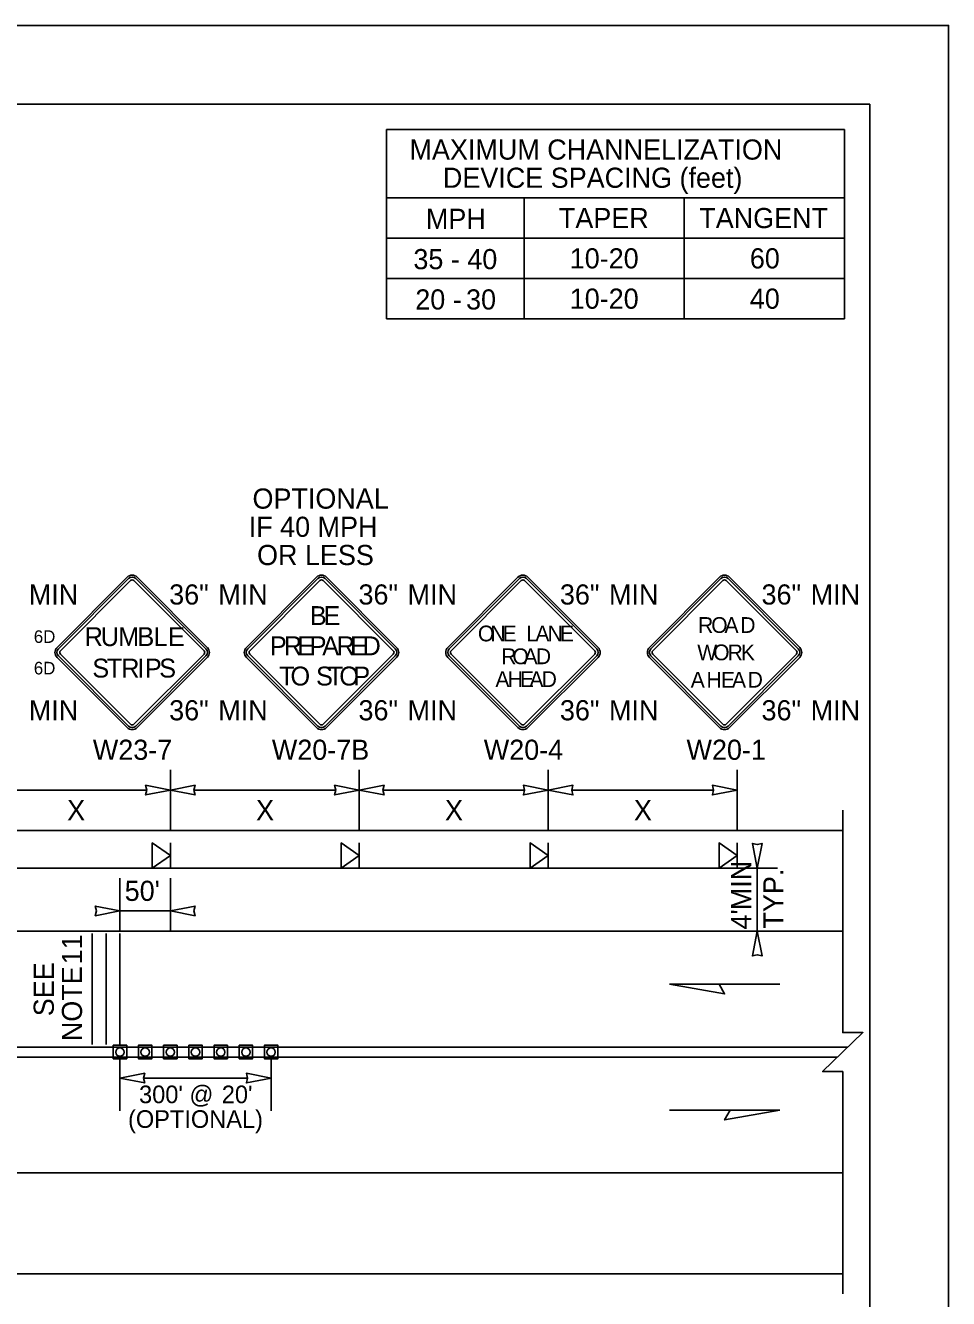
# Model space of a CAD drawing. Extents: x 99998.9 to 100095.7, y 99995 to 100010.7.
# Drawn here: x 100052.4 to 100056.06, y 100005.63 to 100010.69 of the extents above; entities that cross this region are included whole.
import ezdxf

# ---------------------------------------------------------------- set-up
doc = ezdxf.new("R2010")
doc.units = 0
for name, color, linetype in [('RD_ED_ShoulderPavedEdge', 7, 'Continuous'), ('RD_MK_LineDblYellowCenter', 7, 'Continuous'), ('RD_MK_LineEdgeWhite', 7, 'Continuous'), ('SH_GI_PlotLimits', 7, 'Continuous'), ('SH_GI_SheetBorder', 7, 'Continuous'), ('SH_TI_Tables', 7, 'Continuous'), ('TR_SN_ConstructionSigns', 7, 'Continuous'), ('TR_WZ_PortableSignMountBlk-Org', 7, 'Continuous'), ('TR_WZ_TrafficCone', 7, 'Continuous'), ('TR_WZ_WorkZoneDetails', 7, 'Continuous'), ('TR_WZ_WorkZoneTextCurrent', 7, 'Continuous')]:
    doc.layers.add(name, color=color, linetype=linetype)

msp = doc.modelspace()

# ---------------------------------------------------------------- linework, layer by layer
at = {"layer": 'RD_ED_ShoulderPavedEdge'}
for p, q in [((100040.1076, 100007.4923), (100055.6424, 100007.4923)), ((100040.1076, 100005.7323), (100055.6424, 100005.7323))]:
    msp.add_line(p, q, dxfattribs=at)
at = {"layer": 'RD_MK_LineDblYellowCenter'}
for p, q in [((100052.2733, 100006.6323), (100055.6631, 100006.6323)), ((100052.2733, 100006.5923), (100055.6218, 100006.5923))]:
    msp.add_line(p, q, dxfattribs=at)
at = {"layer": 'RD_MK_LineEdgeWhite'}
for p, q in [((100040.1076, 100007.0923), (100055.6424, 100007.0923)), ((100040.1076, 100006.1323), (100055.6424, 100006.1323))]:
    msp.add_line(p, q, dxfattribs=at)
at = {"layer": 'SH_GI_PlotLimits'}
msp.add_lwpolyline([(100039.0625, 99999.6875), (100056.0625, 99999.6875), (100056.0625, 100010.6875), (100039.0625, 100010.6875)], close=True, dxfattribs=at)
at = {"layer": 'SH_GI_SheetBorder'}
for p, q in [((100040, 100010.375), (100055.75, 100010.375)), ((100055.75, 100010.375), (100055.75, 100000))]:
    msp.add_line(p, q, dxfattribs=at)
at = {"layer": 'SH_TI_Tables'}
for p, q in [((100053.8318, 100010.275), (100055.65, 100010.275)), ((100053.8318, 100009.523), (100053.8318, 100010.275)), ((100055.65, 100009.523), (100055.65, 100010.275)), ((100053.8318, 100010.003), (100055.65, 100010.003)), ((100054.3773, 100009.523), (100054.3773, 100010.003)), ((100055.0136, 100009.523), (100055.0136, 100010.003)), ((100053.8318, 100009.843), (100054.3773, 100009.843)), ((100054.3773, 100009.843), (100055.0136, 100009.843)), ((100055.0136, 100009.843), (100055.65, 100009.843)), ((100053.8318, 100009.683), (100054.3773, 100009.683)), ((100054.3773, 100009.683), (100055.0136, 100009.683)), ((100055.0136, 100009.683), (100055.6472, 100009.683)), ((100053.8318, 100009.523), (100055.65, 100009.523))]:
    msp.add_line(p, q, dxfattribs=at)
at = {"layer": 'TR_SN_ConstructionSigns'}
for p, q in [((100052.8019, 100008.4972), (100052.5235, 100008.2188)), ((100052.8075, 100008.4917), (100052.529, 100008.2132)), ((100053.1146, 100008.2132), (100052.8362, 100008.4917)), ((100053.1201, 100008.2188), (100052.8417, 100008.4972)), ((100053.5535, 100008.4972), (100053.275, 100008.2188)), ((100053.559, 100008.4917), (100053.2806, 100008.2132)), ((100053.8661, 100008.2132), (100053.5877, 100008.4917)), ((100053.8717, 100008.2188), (100053.5932, 100008.4972)), ((100054.3532, 100008.4972), (100054.0747, 100008.2188)), ((100054.3587, 100008.4917), (100054.0803, 100008.2132)), ((100054.6658, 100008.2132), (100054.3874, 100008.4917)), ((100054.6714, 100008.2188), (100054.3929, 100008.4972)), ((100055.1535, 100008.4972), (100054.875, 100008.2188)), ((100055.159, 100008.4917), (100054.8806, 100008.2132)), ((100055.4661, 100008.2132), (100055.1877, 100008.4917)), ((100055.4717, 100008.2188), (100055.1932, 100008.4972)), ((100052.5368, 100008.2055), (100052.8152, 100008.4839)), ((100052.8285, 100008.4839), (100053.1069, 100008.2055)), ((100053.2883, 100008.2055), (100053.5667, 100008.4839)), ((100053.58, 100008.4839), (100053.8584, 100008.2055)), ((100054.088, 100008.2055), (100054.3664, 100008.4839)), ((100054.3797, 100008.4839), (100054.6581, 100008.2055)), ((100054.8883, 100008.2055), (100055.1667, 100008.4839)), ((100055.18, 100008.4839), (100055.4584, 100008.2055)), ((100052.529, 100008.1845), (100052.8075, 100007.9061)), ((100052.8152, 100007.9138), (100052.5368, 100008.1923)), ((100053.1069, 100008.1923), (100052.8285, 100007.9138)), ((100052.8362, 100007.9061), (100053.1146, 100008.1845)), ((100053.2806, 100008.1845), (100053.559, 100007.9061)), ((100053.5667, 100007.9138), (100053.2883, 100008.1923)), ((100053.8584, 100008.1923), (100053.58, 100007.9138)), ((100053.5877, 100007.9061), (100053.8661, 100008.1845)), ((100054.0803, 100008.1845), (100054.3587, 100007.9061)), ((100054.3664, 100007.9138), (100054.088, 100008.1923)), ((100054.6581, 100008.1923), (100054.3797, 100007.9138)), ((100054.3874, 100007.9061), (100054.6658, 100008.1845)), ((100054.8806, 100008.1845), (100055.159, 100007.9061)), ((100055.1667, 100007.9138), (100054.8883, 100008.1923)), ((100055.4584, 100008.1923), (100055.18, 100007.9138)), ((100055.1877, 100007.9061), (100055.4661, 100008.1845)), ((100052.5235, 100008.179), (100052.8019, 100007.9006)), ((100052.8417, 100007.9006), (100053.1201, 100008.179)), ((100053.275, 100008.179), (100053.5535, 100007.9006)), ((100053.5932, 100007.9006), (100053.8717, 100008.179)), ((100054.0747, 100008.179), (100054.3532, 100007.9006)), ((100054.3929, 100007.9006), (100054.6714, 100008.179)), ((100054.875, 100008.179), (100055.1535, 100007.9006)), ((100055.1932, 100007.9006), (100055.4717, 100008.179))]:
    msp.add_line(p, q, dxfattribs=at)
for centre, radius, start, end in [((100052.8218, 100008.4773), 0.0281, 45, 135), ((100052.8218, 100008.4773), 0.0203, 45, 135), ((100053.5733, 100008.4773), 0.0281, 45, 135), ((100053.5733, 100008.4773), 0.0203, 45, 135), ((100054.373, 100008.4773), 0.0281, 45, 135), ((100054.373, 100008.4773), 0.0203, 45, 135), ((100055.1733, 100008.4773), 0.0281, 45, 135), ((100055.1733, 100008.4773), 0.0203, 45, 135), ((100052.8218, 100008.4773), 0.00937, 45, 135), ((100053.5733, 100008.4773), 0.00937, 45, 135), ((100054.373, 100008.4773), 0.00937, 45, 135), ((100055.1733, 100008.4773), 0.00937, 45, 135), ((100052.5434, 100008.1989), 0.0281, 135, 225), ((100052.5434, 100008.1989), 0.0203, 135, 225), ((100052.5434, 100008.1989), 0.00937, 135, 225), ((100053.1003, 100008.1989), 0.00937, 315, 45), ((100053.1003, 100008.1989), 0.0203, 315, 45), ((100053.1003, 100008.1989), 0.0281, 315, 45), ((100053.2949, 100008.1989), 0.0281, 135, 225), ((100053.2949, 100008.1989), 0.0203, 135, 225), ((100053.2949, 100008.1989), 0.00937, 135, 225), ((100053.8518, 100008.1989), 0.00937, 315, 45), ((100053.8518, 100008.1989), 0.0203, 315, 45), ((100053.8518, 100008.1989), 0.0281, 315, 45), ((100054.0946, 100008.1989), 0.0281, 135, 225), ((100054.0946, 100008.1989), 0.0203, 135, 225), ((100054.0946, 100008.1989), 0.00937, 135, 225), ((100054.6515, 100008.1989), 0.00937, 315, 45), ((100054.6515, 100008.1989), 0.0203, 315, 45), ((100054.6515, 100008.1989), 0.0281, 315, 45), ((100054.8949, 100008.1989), 0.0281, 135, 225), ((100054.8949, 100008.1989), 0.0203, 135, 225), ((100054.8949, 100008.1989), 0.00937, 135, 225), ((100055.4518, 100008.1989), 0.00937, 315, 45), ((100055.4518, 100008.1989), 0.0203, 315, 45), ((100055.4518, 100008.1989), 0.0281, 315, 45), ((100052.8218, 100007.9205), 0.0281, 225, 315), ((100052.8218, 100007.9205), 0.0203, 225, 315), ((100052.8218, 100007.9205), 0.00937, 225, 315), ((100053.5733, 100007.9205), 0.0281, 225, 315), ((100053.5733, 100007.9205), 0.0203, 225, 315), ((100053.5733, 100007.9205), 0.00937, 225, 315), ((100054.373, 100007.9205), 0.0281, 225, 315), ((100054.373, 100007.9205), 0.0203, 225, 315), ((100054.373, 100007.9205), 0.00937, 225, 315), ((100055.1733, 100007.9205), 0.0281, 225, 315), ((100055.1733, 100007.9205), 0.0203, 225, 315), ((100055.1733, 100007.9205), 0.00937, 225, 315)]:
    msp.add_arc(centre, radius, start, end, dxfattribs=at)
at = {"layer": 'TR_WZ_PortableSignMountBlk-Org'}
for p, q in [((100052.9733, 100007.4422), (100052.9733, 100007.3422)), ((100053.7233, 100007.4422), (100053.7233, 100007.3422)), ((100054.4733, 100007.4422), (100054.4733, 100007.3422)), ((100055.2233, 100007.4422), (100055.2233, 100007.3422))]:
    msp.add_line(p, q, dxfattribs=at)
for points in [[(100052.9733, 100007.3923), (100052.9015, 100007.3422), (100052.9015, 100007.4422)], [(100053.7233, 100007.3923), (100053.6515, 100007.3422), (100053.6515, 100007.4422)], [(100054.4733, 100007.3923), (100054.4015, 100007.3422), (100054.4015, 100007.4422)], [(100055.2233, 100007.3923), (100055.1515, 100007.3422), (100055.1515, 100007.4422)]]:
    msp.add_lwpolyline(points, close=True, dxfattribs=at)
at = {"layer": 'TR_WZ_TrafficCone'}
for points in [[(100052.8, 100006.5857), (100052.7467, 100006.5857), (100052.7467, 100006.639), (100052.8, 100006.639), (100052.8, 100006.5857)], [(100052.8, 100006.639), (100052.7467, 100006.639), (100052.7467, 100006.5857), (100052.8, 100006.5857), (100052.8, 100006.639)], [(100052.9, 100006.5857), (100052.8467, 100006.5857), (100052.8467, 100006.639), (100052.9, 100006.639), (100052.9, 100006.5857)], [(100052.9, 100006.639), (100052.8467, 100006.639), (100052.8467, 100006.5857), (100052.9, 100006.5857), (100052.9, 100006.639)], [(100053, 100006.5857), (100052.9467, 100006.5857), (100052.9467, 100006.639), (100053, 100006.639), (100053, 100006.5857)], [(100053, 100006.639), (100052.9467, 100006.639), (100052.9467, 100006.5857), (100053, 100006.5857), (100053, 100006.639)], [(100053.1, 100006.5857), (100053.0467, 100006.5857), (100053.0467, 100006.639), (100053.1, 100006.639), (100053.1, 100006.5857)], [(100053.1, 100006.639), (100053.0467, 100006.639), (100053.0467, 100006.5857), (100053.1, 100006.5857), (100053.1, 100006.639)], [(100053.2, 100006.5857), (100053.1467, 100006.5857), (100053.1467, 100006.639), (100053.2, 100006.639), (100053.2, 100006.5857)], [(100053.2, 100006.639), (100053.1467, 100006.639), (100053.1467, 100006.5857), (100053.2, 100006.5857), (100053.2, 100006.639)], [(100053.3, 100006.5857), (100053.2467, 100006.5857), (100053.2467, 100006.639), (100053.3, 100006.639), (100053.3, 100006.5857)], [(100053.3, 100006.639), (100053.2467, 100006.639), (100053.2467, 100006.5857), (100053.3, 100006.5857), (100053.3, 100006.639)], [(100053.4, 100006.5857), (100053.3467, 100006.5857), (100053.3467, 100006.639), (100053.4, 100006.639), (100053.4, 100006.5857)], [(100053.4, 100006.639), (100053.3467, 100006.639), (100053.3467, 100006.5857), (100053.4, 100006.5857), (100053.4, 100006.639)]]:
    msp.add_lwpolyline(points, dxfattribs=at)
for centre in [(100052.7733, 100006.6123), (100052.8733, 100006.6123), (100052.9733, 100006.6123), (100053.0733, 100006.6123), (100053.1733, 100006.6123), (100053.2733, 100006.6123), (100053.3733, 100006.6123)]:
    msp.add_circle(centre, 0.0167, dxfattribs=at)
at = {"layer": 'TR_WZ_WorkZoneDetails'}
for p, q in [((100052.9733, 100007.4923), (100052.9733, 100007.7323)), ((100053.7233, 100007.4923), (100053.7233, 100007.7323)), ((100054.4733, 100007.4923), (100054.4733, 100007.7323)), ((100055.2233, 100007.4921), (100055.2233, 100007.7323)), ((100052.3171, 100007.6523), (100052.8796, 100007.6523)), ((100053.0671, 100007.6523), (100053.6296, 100007.6523)), ((100053.8171, 100007.6523), (100054.3796, 100007.6523)), ((100054.5671, 100007.6523), (100055.1296, 100007.6523)), ((100052.2233, 100007.3422), (100055.2233, 100007.3422)), ((100055.2233, 100007.3422), (100055.3833, 100007.3422)), ((100055.3033, 100007.3422), (100055.3033, 100007.0923)), ((100052.7733, 100007.0923), (100052.7733, 100007.3023)), ((100052.9733, 100007.3023), (100052.9733, 100007.0923)), ((100052.7733, 100007.1723), (100052.9733, 100007.1723)), ((100052.6628, 100006.6423), (100052.6628, 100007.0823)), ((100052.7185, 100006.6423), (100052.7185, 100007.0823)), ((100052.7733, 100006.6423), (100052.7733, 100007.0823)), ((100055.2233, 100007.0923), (100055.3833, 100007.0923)), ((100055.1513, 100006.8816), (100055.3924, 100006.8816)), ((100052.7733, 100006.589), (100052.7733, 100006.379)), ((100053.3733, 100006.379), (100053.3733, 100006.589)), ((100053.2796, 100006.509), (100052.8671, 100006.509)), ((100055.1959, 100006.3816), (100054.9548, 100006.3816))]:
    msp.add_line(p, q, dxfattribs=at)
for points in [[(100052.9733, 100007.6523), (100052.8751, 100007.6331), (100052.8796, 100007.6523), (100052.8751, 100007.6716)], [(100052.9733, 100007.6523), (100053.0716, 100007.6331), (100053.0671, 100007.6523), (100053.0716, 100007.6716)], [(100053.7233, 100007.6523), (100053.6251, 100007.6331), (100053.6296, 100007.6523), (100053.6251, 100007.6716)], [(100053.7233, 100007.6523), (100053.8216, 100007.6331), (100053.8171, 100007.6523), (100053.8216, 100007.6716)], [(100054.4733, 100007.6523), (100054.3751, 100007.6331), (100054.3796, 100007.6523), (100054.3751, 100007.6716)], [(100054.4733, 100007.6523), (100054.5716, 100007.6331), (100054.5671, 100007.6523), (100054.5716, 100007.6716)], [(100055.2233, 100007.6523), (100055.1251, 100007.6331), (100055.1296, 100007.6523), (100055.1251, 100007.6716)], [(100055.3033, 100007.3422), (100055.2841, 100007.4405), (100055.3033, 100007.436), (100055.3226, 100007.4405)], [(100052.7733, 100007.1723), (100052.6751, 100007.1916), (100052.6796, 100007.1723), (100052.6751, 100007.1531)], [(100052.9733, 100007.1723), (100053.0716, 100007.1916), (100053.0671, 100007.1723), (100053.0716, 100007.1531)], [(100055.3033, 100007.0923), (100055.2841, 100006.9941), (100055.3033, 100006.9986), (100055.3226, 100006.9941)], [(100054.9548, 100006.8816), (100055.1736, 100006.843), (100055.1513, 100006.8816)], [(100052.7733, 100006.509), (100052.8716, 100006.4897), (100052.8671, 100006.509), (100052.8716, 100006.5283)], [(100053.3733, 100006.509), (100053.2751, 100006.4897), (100053.2796, 100006.509), (100053.2751, 100006.5283)], [(100055.3924, 100006.3816), (100055.1736, 100006.343), (100055.1959, 100006.3816)]]:
    msp.add_lwpolyline(points, close=True, dxfattribs=at)
msp.add_lwpolyline([(100055.6424, 100005.6523), (100055.6424, 100006.5349), (100055.5624, 100006.5349), (100055.7225, 100006.6898), (100055.6424, 100006.6898), (100055.6424, 100007.5723)], dxfattribs=at)

# ---------------------------------------------------------------- texts
at = {"layer": 'SH_TI_Tables'}
for s, p in [('MAXIMUM CHANNELIZATION', (100053.9227, 100010.155)), ('DEVICE SPACING (feet)', (100054.0553, 100010.043)), ('MPH', (100053.9878, 100009.8799)), ('TAPER', (100054.5157, 100009.883)), ('TANGENT', (100055.0731, 100009.883)), ('10-20', (100054.5588, 100009.723)), ('60', (100055.2737, 100009.723)), ('35', (100053.9381, 100009.7199)), ('- 40', (100054.0869, 100009.7199)), ('20', (100053.9456, 100009.5599)), ('30', (100054.1472, 100009.5599)), ('10-20', (100054.5588, 100009.563)), ('40', (100055.2737, 100009.563)), ('-', (100054.0944, 100009.5599))]:
    msp.add_text(s, height=0.08, dxfattribs=at).set_placement(p)
at = {"layer": 'TR_SN_ConstructionSigns'}
for s, height, p in [('OPTIONAL', 0.08, (100053.2994, 100008.7694)), ('IF 40 MPH', 0.08, (100053.2843, 100008.6574)), ('OR LESS', 0.08, (100053.3175, 100008.5454)), ('B', 0.075, (100053.5271, 100008.3074)), ('E', 0.075, (100053.5814, 100008.3074)), ('R', 0.0625, (100055.0683, 100008.2762)), ('O', 0.0625, (100055.1204, 100008.2762)), ('A', 0.0625, (100055.1732, 100008.2762)), ('D', 0.0625, (100055.2359, 100008.2762)), ('6D', 0.05, (100052.4313, 100008.2364)), ('R', 0.075, (100052.6332, 100008.2239)), ('U', 0.075, (100052.697, 100008.2239)), ('M', 0.075, (100052.766, 100008.2239)), ('B', 0.075, (100052.8425, 100008.2239)), ('L', 0.075, (100052.9062, 100008.2239)), ('E', 0.075, (100052.964, 100008.2239)), ('O', 0.0625, (100054.1943, 100008.2426)), ('N', 0.0625, (100054.2437, 100008.2426)), ('E', 0.0625, (100054.2924, 100008.2426)), ('L', 0.0625, (100054.3868, 100008.2426)), ('A', 0.0625, (100054.4224, 100008.2426)), ('N', 0.0625, (100054.4712, 100008.2426)), ('E', 0.0625, (100054.5199, 100008.2426)), ('P', 0.075, (100053.3684, 100008.1874)), ('R', 0.075, (100053.4237, 100008.1874)), ('E', 0.075, (100053.4769, 100008.1874)), ('P', 0.075, (100053.5264, 100008.1874)), ('A', 0.075, (100053.5763, 100008.1874)), ('R', 0.075, (100053.6335, 100008.1874)), ('E', 0.075, (100053.6868, 100008.1874)), ('D', 0.075, (100053.7362, 100008.1874)), ('R', 0.0625, (100054.2868, 100008.152)), ('O', 0.0625, (100054.3312, 100008.152)), ('A', 0.0625, (100054.3755, 100008.152)), ('D', 0.0625, (100054.4243, 100008.152)), ('W', 0.0625, (100055.065, 100008.1676)), ('O', 0.0625, (100055.1282, 100008.1676)), ('R', 0.0625, (100055.1855, 100008.1676)), ('K', 0.0625, (100055.2379, 100008.1676)), ('6D', 0.05, (100052.4313, 100008.1114)), ('S', 0.075, (100052.6636, 100008.0989)), ('T', 0.075, (100052.7206, 100008.0989)), ('R', 0.075, (100052.7783, 100008.0989)), ('I', 0.075, (100052.8421, 100008.0989)), ('P', 0.075, (100052.8721, 100008.0989)), ('S', 0.075, (100052.9291, 100008.0989)), ('T', 0.075, (100053.4051, 100008.0674)), ('O', 0.075, (100053.4502, 100008.0674)), ('S', 0.075, (100053.5516, 100008.0674)), ('T', 0.075, (100053.5988, 100008.0674)), ('O', 0.075, (100053.6439, 100008.0674)), ('P', 0.075, (100053.6996, 100008.0674)), ('A', 0.0625, (100054.2637, 100008.0614)), ('H', 0.0625, (100054.3124, 100008.0614)), ('E', 0.0625, (100054.3612, 100008.0614)), ('A', 0.0625, (100054.3987, 100008.0614)), ('D', 0.0625, (100054.4474, 100008.0614)), ('A', 0.0625, (100055.039, 100008.0591)), ('H', 0.0625, (100055.1015, 100008.0591)), ('E', 0.0625, (100055.159, 100008.0591)), ('A', 0.0625, (100055.2027, 100008.0591)), ('D', 0.0625, (100055.2652, 100008.0591))]:
    msp.add_text(s, height=height, dxfattribs=at).set_placement(p)
for s, p in [('MIN', (100052.4114, 100008.3887)), ('36"', (100052.9686, 100008.3887)), ('MIN', (100053.1636, 100008.3887)), ('36"', (100053.7201, 100008.3887)), ('MIN', (100053.9151, 100008.3887)), ('36"', (100054.5198, 100008.3887)), ('MIN', (100054.7148, 100008.3887)), ('36"', (100055.3201, 100008.3887)), ('MIN', (100055.5151, 100008.3887)), ('MIN', (100052.4114, 100007.9291)), ('36"', (100052.9686, 100007.9291)), ('MIN', (100053.1636, 100007.9291)), ('36"', (100053.7201, 100007.9291)), ('MIN', (100053.9151, 100007.9291)), ('36"', (100054.5198, 100007.9291)), ('MIN', (100054.7148, 100007.9291)), ('36"', (100055.3201, 100007.9291)), ('MIN', (100055.5151, 100007.9291)), ('W23-7', (100052.6656, 100007.7723)), ('W20-7B', (100053.3763, 100007.7723)), ('W20-4', (100054.2176, 100007.7723)), ('W20-1', (100055.0224, 100007.7723))]:
    msp.add_text(s, height=0.08, rotation=360, dxfattribs=at).set_placement(p)
at = {"layer": 'TR_WZ_WorkZoneDetails'}
for s, p in [('11', (100052.6228, 100006.9604)), ('SEE', (100052.5108, 100006.7544)), ('NOTE', (100052.6228, 100006.6555))]:
    msp.add_text(s, height=0.08, rotation=90, dxfattribs=at).set_placement(p)
at = {"layer": 'TR_WZ_WorkZoneTextCurrent'}
for s, height, p in [('X', 0.08, (100052.5636, 100007.5323)), ('X', 0.08, (100053.3136, 100007.5323)), ('X', 0.08, (100054.0636, 100007.5323)), ('X', 0.08, (100054.8136, 100007.5323)), ("50'", 0.08, (100052.7921, 100007.2123)), ("300' @", 0.07, (100052.8491, 100006.4093)), ("20'", 0.07, (100053.1775, 100006.4093)), ('(OPTIONAL)', 0.07, (100052.8053, 100006.3113))]:
    msp.add_text(s, height=height, dxfattribs=at).set_placement(p)
for s, p in [('MIN', (100055.2793, 100007.1754)), ('TYP.', (100055.4073, 100007.1026)), ("4'", (100055.2793, 100007.0989))]:
    msp.add_text(s, height=0.08, rotation=90, dxfattribs=at).set_placement(p)

doc.saveas('drawing.dxf')
